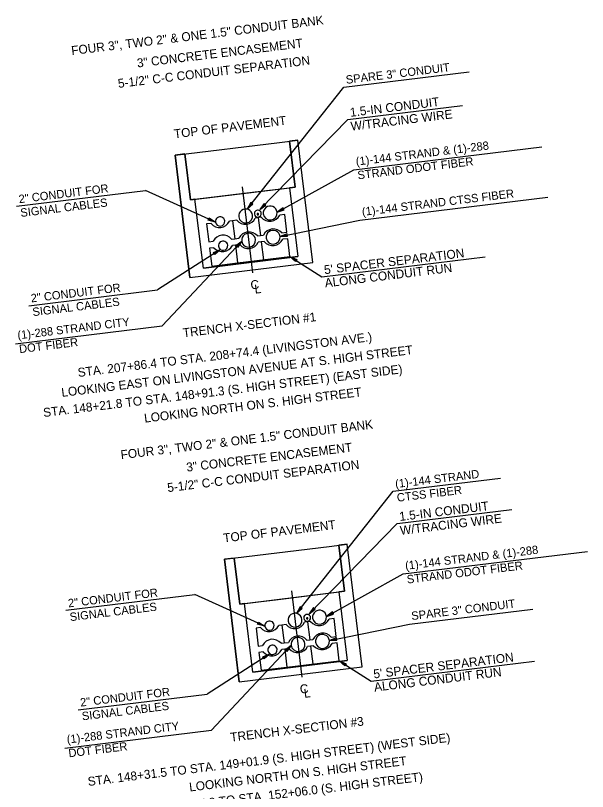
# Model space of a CAD drawing. Extents: x 91401 to 1830080, y 35587 to 712188.
# Drawn here: x 1826997 to 1827382, y 711328 to 711851 of the extents above; entities that cross this region are included whole.
import ezdxf

# ---------------------------------------------------------------- set-up
doc = ezdxf.new("R2010")
doc.units = 0
doc.layers.add('Default', color=7, linetype='Continuous')
doc.layers.add('SH_Text', color=7, linetype='Continuous')

# ---------------------------------------------------------------- blocks, each defined once
blk = doc.blocks.new('POINT_DISPLAY')
at = {"layer": 'Default'}
blk.add_line((0, 0), (0, 0), dxfattribs=at)

msp = doc.modelspace()

# ---------------------------------------------------------------- linework, layer by layer
at = {"layer": 'SH_Text'}
for p, q in [((1827217.82, 711802.36), (1827302.36, 711812.69)), ((1827152.74, 711720.05), (1827217.82, 711802.36)), ((1827220.49, 711780.56), (1827297.85, 711790.01)), ((1827161.16, 711719.86), (1827220.49, 711780.56)), ((1827186.9, 711766.63), (1827181.31, 711765.95)), ((1827185.09, 711734.99), (1827181.31, 711765.95)), ((1827196.98, 711684.11), (1827186.9, 711766.63)), ((1827224.63, 711746.62), (1827351.31, 711762.09)), ((1827110.78, 711757.34), (1827104.07, 711756.52)), ((1827104.07, 711756.52), (1827114.14, 711674)), ((1827114.56, 711726.38), (1827110.78, 711757.34)), ((1827172.89, 711718.06), (1827224.63, 711746.62)), ((1826997.26, 711722.17), (1827084.16, 711732.78)), ((1827131.36, 711711.42), (1827084.16, 711732.78)), ((1827149.27, 711735.2), (1827156.37, 711677.12)), ((1827181.26, 711734.52), (1827186.91, 711688.2)), ((1827228.77, 711712.72), (1827355.45, 711728.18)), ((1827117.53, 711726.74), (1827114.56, 711726.38)), ((1827123.19, 711680.42), (1827117.53, 711726.74)), ((1827174.88, 711701.72), (1827228.77, 711712.72)), ((1827149.01, 711698.57), (1827095.33, 711641.36)), ((1827134.73, 711692.85), (1827092.36, 711665.64)), ((1827123.19, 711680.42), (1827186.91, 711688.2)), ((1827123.19, 711680.42), (1827186.91, 711688.2)), ((1827123.19, 711680.42), (1827186.91, 711688.2)), ((1827186.91, 711688.2), (1827123.19, 711680.42)), ((1827181.54, 711688.16), (1827203.03, 711674.43)), ((1827203.03, 711674.43), (1827313.23, 711687.89)), ((1827114.14, 711674), (1827196.98, 711684.11)), ((1827114.14, 711674), (1827196.98, 711684.11)), ((1827005.46, 711655.03), (1827092.36, 711665.64)), ((1826996.54, 711629.3), (1827095.33, 711641.36)), ((1827251.09, 711529.9), (1827323.58, 711538.75)), ((1827186.01, 711447.59), (1827251.09, 711529.9)), ((1827253.75, 711508.1), (1827331.12, 711517.54)), ((1827194.43, 711447.39), (1827253.75, 711508.1)), ((1827220.17, 711494.17), (1827214.58, 711493.48)), ((1827218.36, 711462.53), (1827214.58, 711493.48)), ((1827230.25, 711411.64), (1827220.17, 711494.17)), ((1827257.9, 711474.15), (1827382.13, 711489.32)), ((1827144.04, 711484.87), (1827137.33, 711484.05)), ((1827137.33, 711484.05), (1827147.41, 711401.53)), ((1827147.82, 711453.91), (1827144.04, 711484.87)), ((1827206.16, 711445.6), (1827257.9, 711474.15)), ((1827030.53, 711449.7), (1827117.43, 711460.31)), ((1827164.63, 711438.95), (1827117.43, 711460.31)), ((1827182.54, 711462.74), (1827189.63, 711404.66)), ((1827214.52, 711462.06), (1827220.18, 711415.74)), ((1827150.8, 711454.28), (1827147.82, 711453.91)), ((1827156.46, 711407.96), (1827150.8, 711454.28)), ((1827262.04, 711440.25), (1827345.33, 711450.42)), ((1827208.15, 711429.26), (1827262.04, 711440.25)), ((1827182.28, 711426.1), (1827128.59, 711368.89)), ((1827168, 711420.38), (1827125.63, 711393.17)), ((1827156.46, 711407.96), (1827220.18, 711415.74)), ((1827156.46, 711407.96), (1827220.18, 711415.74)), ((1827156.46, 711407.96), (1827220.18, 711415.74)), ((1827220.18, 711415.74), (1827156.46, 711407.96)), ((1827214.81, 711415.69), (1827236.3, 711401.97)), ((1827236.3, 711401.97), (1827346.5, 711415.42)), ((1827147.41, 711401.53), (1827230.25, 711411.64)), ((1827147.41, 711401.53), (1827230.25, 711411.64)), ((1827038.73, 711382.56), (1827125.63, 711393.17)), ((1827029.81, 711356.83), (1827128.59, 711368.89))]:
    msp.add_line(p, q, dxfattribs=at)
for points in [[(1827104.07, 711756.52), (1827174.61, 711765.13), (1827186.9, 711766.63), (1827186.9, 711766.63)], [(1827110.78, 711757.34), (1827114.56, 711726.38), (1827185.09, 711734.99), (1827181.31, 711765.95)], [(1827181.31, 711765.95), (1827185.09, 711734.99), (1827181.26, 711734.52)], [(1827196.98, 711684.11), (1827186.9, 711766.63)], [(1827114.14, 711674), (1827104.07, 711756.52)], [(1827117.53, 711726.74), (1827158.1, 711731.7), (1827181.26, 711734.52), (1827186.91, 711688.2)], [(1827117.53, 711726.74), (1827175.91, 711733.87), (1827181.26, 711734.52), (1827186.91, 711688.2)], [(1827117.53, 711726.74), (1827140.28, 711729.52), (1827181.26, 711734.52), (1827186.91, 711688.2)], [(1827123.19, 711680.42), (1827117.53, 711726.74)], [(1827123.19, 711680.42), (1827117.53, 711726.74)], [(1827176.15, 711704.07), (1827179.54, 711704.49), (1827178.07, 711716.53), (1827174.68, 711716.11)], [(1827142.81, 711712.22), (1827140.78, 711711.97)], [(1827145.73, 711712.58), (1827142.81, 711712.22), (1827144.28, 711700.18)], [(1827162.23, 711714.59), (1827158.18, 711714.1)], [(1827160.21, 711714.34), (1827161.68, 711702.31)], [(1827128.33, 711710.45), (1827125.4, 711710.09), (1827126.87, 711698.06), (1827129.8, 711698.41)], [(1827159.65, 711702.06), (1827163.7, 711702.55)], [(1827142.25, 711699.93), (1827144.28, 711700.18)], [(1827144.8, 711695.89), (1827142.77, 711695.64)], [(1827144.28, 711700.18), (1827147.2, 711700.54)], [(1827147.72, 711696.25), (1827144.8, 711695.89), (1827146.27, 711683.85)], [(1827146.27, 711683.85), (1827181.54, 711688.16), (1827180.07, 711700.19), (1827176.68, 711699.78)], [(1827164.23, 711698.26), (1827160.18, 711697.77)], [(1827162.2, 711698.01), (1827163.67, 711685.98)], [(1827130.32, 711694.12), (1827127.4, 711693.76), (1827128.87, 711681.73), (1827146.27, 711683.85)], [(1827137.33, 711484.05), (1827207.88, 711492.66), (1827220.17, 711494.17), (1827220.17, 711494.17)], [(1827144.04, 711484.87), (1827147.82, 711453.91), (1827218.36, 711462.53), (1827214.58, 711493.48)], [(1827214.58, 711493.48), (1827218.36, 711462.53), (1827214.52, 711462.06)], [(1827230.25, 711411.64), (1827220.17, 711494.17)], [(1827147.41, 711401.53), (1827137.33, 711484.05)], [(1827150.8, 711454.28), (1827191.36, 711459.23), (1827214.52, 711462.06), (1827220.18, 711415.74)], [(1827150.8, 711454.28), (1827209.18, 711461.4), (1827214.52, 711462.06), (1827220.18, 711415.74)], [(1827150.8, 711454.28), (1827173.55, 711457.05), (1827214.52, 711462.06), (1827220.18, 711415.74)], [(1827156.46, 711407.96), (1827150.8, 711454.28)], [(1827156.46, 711407.96), (1827150.8, 711454.28)], [(1827176.07, 711439.75), (1827174.05, 711439.5)], [(1827179, 711440.11), (1827176.07, 711439.75), (1827177.54, 711427.71)], [(1827195.5, 711442.12), (1827191.45, 711441.63)], [(1827193.48, 711441.88), (1827194.95, 711429.84)], [(1827209.42, 711431.61), (1827212.81, 711432.02), (1827211.34, 711444.06), (1827207.95, 711443.64)], [(1827161.6, 711437.98), (1827158.67, 711437.63), (1827160.14, 711425.59), (1827163.07, 711425.95)], [(1827192.92, 711429.59), (1827196.97, 711430.09)], [(1827175.52, 711427.47), (1827177.54, 711427.71)], [(1827177.54, 711427.71), (1827180.47, 711428.07)], [(1827180.99, 711423.78), (1827178.07, 711423.42), (1827179.54, 711411.38)], [(1827179.54, 711411.38), (1827214.81, 711415.69), (1827213.34, 711427.73), (1827209.95, 711427.31)], [(1827197.5, 711425.79), (1827193.44, 711425.3)], [(1827195.47, 711425.55), (1827196.94, 711413.51)], [(1827163.59, 711421.65), (1827160.67, 711421.3), (1827162.14, 711409.26), (1827179.54, 711411.38)], [(1827178.07, 711423.42), (1827176.04, 711423.17)]]:
    msp.add_lwpolyline(points, dxfattribs=at)
for points in [[(1827156.5, 711723.46), (1827155.19, 711724.49), (1827152.74, 711720.05)], [(1827165.28, 711722.82), (1827164.09, 711723.99), (1827161.16, 711719.86)], [(1827177.72, 711719.59), (1827176.97, 711721.07), (1827172.89, 711718.06)], [(1827126.46, 711712.72), (1827127.15, 711714.24), (1827131.36, 711711.42)], [(1827179.95, 711701.92), (1827179.61, 711703.55), (1827174.88, 711701.72)], [(1827146.2, 711694.35), (1827144.98, 711695.49), (1827149.01, 711698.57)], [(1827130.98, 711689.44), (1827130.07, 711690.85), (1827134.73, 711692.85)], [(1827186.2, 711686.16), (1827185.3, 711684.76), (1827181.54, 711688.16)], [(1827189.77, 711450.99), (1827188.46, 711452.03), (1827186.01, 711447.59)], [(1827198.55, 711450.35), (1827197.36, 711451.52), (1827194.43, 711447.39)], [(1827210.99, 711447.12), (1827210.24, 711448.61), (1827206.16, 711445.6)], [(1827159.73, 711440.25), (1827160.42, 711441.77), (1827164.63, 711438.95)], [(1827213.22, 711429.45), (1827212.88, 711431.08), (1827208.15, 711429.26)], [(1827179.47, 711421.88), (1827178.25, 711423.02), (1827182.28, 711426.1)], [(1827164.24, 711416.98), (1827163.34, 711418.38), (1827168, 711420.38)], [(1827219.46, 711413.69), (1827218.57, 711412.29), (1827214.81, 711415.69)]]:
    msp.add_lwpolyline(points, close=True, dxfattribs=at)
for centre, radius, start, end in [((1827168.22, 711717.5), 4.7, 6.9614, 186.9614), ((1827151.68, 711715.48), 4.7, 6.9614, 186.9614), ((1827159.88, 711717.08), 2.35, 6.9614, 186.9614), ((1827159.88, 711717.08), 2.35, 186.9614, 6.9614), ((1827159.86, 711716.67), 0.5, 6.9614, 186.9614), ((1827159.86, 711716.67), 0.5, 186.9614, 6.9614), ((1827168.22, 711717.5), 4.7, 186.9614, 6.9614), ((1827134.07, 711715.21), 7.45, 219.6485, 334.2743), ((1827134.47, 711711.8), 3.13, 6.9614, 186.9614), ((1827134.47, 711711.8), 3.13, 186.9614, 6.9614), ((1827151.47, 711717.33), 7.45, 219.6485, 334.2743), ((1827151.68, 711715.48), 4.7, 186.9614, 6.9614), ((1827167.97, 711719.35), 7.45, 219.6485, 334.2743), ((1827170.42, 711699.32), 7.45, 39.6485, 154.2743), ((1827136.51, 711695.18), 7.45, 39.6485, 154.2743), ((1827153.91, 711697.3), 7.45, 39.6485, 154.2743), ((1827153.68, 711699.14), 4.7, 6.9614, 186.9614), ((1827170.22, 711701.15), 4.7, 6.9614, 186.9614), ((1827170.22, 711701.15), 4.7, 186.9614, 6.9614), ((1827136.06, 711698.88), 7.45, 219.6485, 334.2743), ((1827136.47, 711695.46), 3.13, 6.9614, 186.9614), ((1827136.47, 711695.46), 3.13, 186.9614, 6.9614), ((1827153.46, 711701), 7.45, 219.6485, 334.2743), ((1827153.68, 711699.14), 4.7, 186.9614, 6.9614), ((1827169.97, 711703.02), 7.45, 219.6485, 334.2743), ((1827201.49, 711445.03), 4.7, 6.9614, 186.9614), ((1827184.95, 711443.01), 4.7, 6.9614, 186.9614), ((1827193.15, 711444.62), 2.35, 6.9614, 186.9614), ((1827193.15, 711444.62), 2.35, 186.9614, 6.9614), ((1827193.13, 711444.21), 0.5, 6.9614, 186.9614), ((1827201.49, 711445.03), 4.7, 186.9614, 6.9614), ((1827167.33, 711442.74), 7.45, 219.6485, 334.2743), ((1827167.74, 711439.33), 3.13, 6.9614, 186.9614), ((1827167.74, 711439.33), 3.13, 186.9614, 6.9614), ((1827184.74, 711444.86), 7.45, 219.6485, 334.2743), ((1827184.95, 711443.01), 4.7, 186.9614, 6.9614), ((1827193.13, 711444.21), 0.5, 186.9614, 6.9614), ((1827201.24, 711446.88), 7.45, 219.6485, 334.2743), ((1827203.69, 711426.85), 7.45, 39.6485, 154.2743), ((1827169.78, 711422.71), 7.45, 39.6485, 154.2743), ((1827187.18, 711424.84), 7.45, 39.6485, 154.2743), ((1827186.95, 711426.67), 4.7, 6.9614, 186.9614), ((1827203.49, 711428.69), 4.7, 6.9614, 186.9614), ((1827203.49, 711428.69), 4.7, 186.9614, 6.9614), ((1827169.73, 711422.99), 3.13, 6.9614, 186.9614), ((1827186.73, 711428.53), 7.45, 219.6485, 334.2743), ((1827186.95, 711426.67), 4.7, 186.9614, 6.9614), ((1827203.23, 711430.55), 7.45, 219.6485, 334.2743), ((1827169.33, 711426.41), 7.45, 219.6485, 334.2743), ((1827169.73, 711422.99), 3.13, 186.9614, 6.9614)]:
    msp.add_arc(centre, radius, start, end, dxfattribs=at)

# ---------------------------------------------------------------- block references
at = {"layer": 'SH_Text', "xscale": 1.5748, "yscale": 1.5748000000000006, "rotation": 6.96142799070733}
for p in [(1827155.53, 711683.98), (1827188.8, 711411.51)]:
    msp.add_blockref('POINT_DISPLAY', p, dxfattribs=at)

# ---------------------------------------------------------------- texts
at = {"layer": 'SH_Text'}
for s, height, p in [('FOUR 3", TWO 2" & ONE 1.5" CONDUIT BANK', 6, (1827034.51, 711823.96)), ('3" CONCRETE ENCASEMENT', 6, (1827078.78, 711815.56)), ('5-1/2" C-C CONDUIT SEPARATION', 6, (1827065.95, 711801.8)), ('SPARE 3" CONDUIT', 5.6, (1827219.57, 711804.54)), ('1.5-IN CONDUIT', 6, (1827222.36, 711782.32)), ('W/TRACING WIRE', 6, (1827222.87, 711772.97)), ('TOP OF PAVEMENT', 6, (1827103.71, 711767.83)), ('(1)-144 STRAND & (1)-288 ', 5.6, (1827226.29, 711749.42)), ('STRAND ODOT FIBER ', 5.6, (1827227.43, 711740.16)), ('2" CONDUIT FOR ', 5.6, (1826999.04, 711724.08)), ('(1)-144 STRAND CTSS FIBER', 5.6, (1827230.43, 711715.52)), ('SIGNAL CABLES', 5.6, (1827000.17, 711714.81)), ("5' SPACER SEPARATION", 6, (1827204.91, 711676.19)), ('ALONG CONDUIT RUN', 6, (1827205.35, 711667.31)), ('2" CONDUIT FOR ', 5.6, (1827007.2, 711657.2)), ('C', 6, (1827155.32, 711665.88)), ('L', 6, (1827158.01, 711663.09)), ('SIGNAL CABLES', 5.6, (1827008.33, 711647.94)), ('TRENCH X-SECTION #1', 6, (1827109.71, 711633.7)), ('(1)-288 STRAND CITY ', 5.6, (1826998.19, 711632.28)), ('DOT FIBER', 5.6, (1826999.32, 711623.01)), ('STA. 207+86.4 TO STA. 208+74.4 (LIVINGSTON AVE.)', 6, (1827038.86, 711606.95)), ('LOOKING EAST ON LIVINGSTON AVENUE AT S. HIGH STREET', 6, (1827027.84, 711593.51)), ('STA. 148+21.8 TO STA. 148+91.3 (S. HIGH STREET) (EAST SIDE)', 6, (1827015.54, 711579.92)), ('LOOKING NORTH ON S. HIGH STREET', 6, (1827083.64, 711576.15)), ('FOUR 3", TWO 2" & ONE 1.5" CONDUIT BANK', 6, (1827067.78, 711551.49)), ('3" CONCRETE ENCASEMENT', 6, (1827112.05, 711543.09)), ('5-1/2" C-C CONDUIT SEPARATION', 6, (1827099.22, 711529.33)), ('(1)-144 STRAND', 5.6, (1827252.83, 711532.07)), ('CTSS FIBER', 5.6, (1827253.97, 711522.81)), ('1.5-IN CONDUIT', 6, (1827255.63, 711509.85)), ('W/TRACING WIRE', 6, (1827256.13, 711500.5)), ('TOP OF PAVEMENT', 6, (1827136.98, 711495.36)), ('(1)-144 STRAND & (1)-288 ', 5.6, (1827259.56, 711476.96)), ('STRAND ODOT FIBER', 5.6, (1827260.69, 711467.69)), ('2" CONDUIT FOR ', 5.6, (1827032.3, 711451.61)), ('SIGNAL CABLES', 5.6, (1827033.43, 711442.34)), ('SPARE 3" CONDUIT', 5.6, (1827263.7, 711443.05)), ("5' SPACER SEPARATION", 6, (1827238.18, 711403.72)), ('ALONG CONDUIT RUN', 6, (1827238.62, 711394.85)), ('2" CONDUIT FOR ', 5.6, (1827040.47, 711384.73)), ('C', 6, (1827188.59, 711393.42)), ('L', 6, (1827191.28, 711390.63)), ('SIGNAL CABLES', 5.6, (1827041.6, 711375.47)), ('TRENCH X-SECTION #3', 6, (1827141.71, 711361.07)), ('(1)-288 STRAND CITY ', 5.6, (1827031.45, 711359.81)), ('STA. 148+31.5 TO STA. 149+01.9 (S. HIGH STREET) (WEST SIDE)', 6, (1827045.61, 711331.24)), ('DOT FIBER', 5.6, (1827032.59, 711350.55)), ('LOOKING NORTH ON S. HIGH STREET', 6, (1827114, 711327.5)), ('STA. 151+35.8 TO STA. 152+06.0 (S. HIGH STREET)', 6, (1827078.44, 711311.07))]:
    msp.add_text(s, height=height, rotation=6.9614, dxfattribs=at).set_placement(p)

doc.saveas('drawing.dxf')
